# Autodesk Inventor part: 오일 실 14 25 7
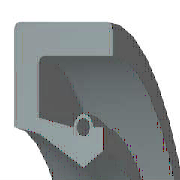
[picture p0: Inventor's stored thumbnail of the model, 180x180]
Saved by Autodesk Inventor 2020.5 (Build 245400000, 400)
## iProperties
Created: 2012-02
Part Number: 오일 실 14 25 7
Material: 고무
Description: 오일 실 - 스프링 장착, 금속 케이스 SM
Document SubType Name: Modeling
Standard: JIS B 2402
Designer: mdu-01
Standards Organization: JIS
Language: ko-KR
Size Designation: 14 25 7 A
Categories: <MemberInstance><Categories><Category DisplayName="샤프트 부품" InternalName="7f7aeb1f-a693-4053-b835-cee3144e0d98" Mnemonic="SHFT"><Category DisplayName="실링" Intern
Density: 0.93 g/cm^3
Appearance: Rubber-Black
IsCustomPart: 1
Author: mdu-01
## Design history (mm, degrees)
body "Solid1"
revolve "회전1" stored, may be unused: angle "d33" = 360 deg
fillet "모깎기1" dims "d34" = 0.35 (= 0.05 x b)
chamfer "모따기1" distance "d35" = 0.7 (= 0.1 x b); stored, may be unused: second distance "d36" = 0.35 (= 0.05 x b), angle "d41" = 45 deg
sketch "스케치2"
  geometry: L1 (8.336, -5.158)-(8.853, -7); L2 (7.786, -4.55)-(8.336, -5.158); L3 (7, -1.75)-(7.786, -4.55); L4 (7.733, -0.875)-(7, -1.75); L5 (8.963, -0.875)-(7.733, -0.875); L6 (8.963, -1.575)-(8.963, -0.875); L7 (8.963, -5.25)-(8.963, -2.975); L8 (10.3, -5.25)-(8.963, -5.25); L9 (11.4, -1.75)-(10.3, -5.25); L10 (11.4, 0)-(11.4, -1.75); L11 (12.5, 0)-(11.4, 0); L12 (12.5, -7)-(12.5, 0); L13 (8.853, -7)-(12.5, -7); L14 (0, -9.6)-(0, 1.6) reference; L15 (28, 0)-(14, 0) reference; A1 r 0.7 centre (8.963, -2.275) between (8.963, -2.975) and (8.963, -1.575)
  constraints: 26 end point, 4 horizontal, 4 vertical, 2 point on circle, 1 centre point, 1 collinear, 1 parallel
  dimensions: "d2" = 7 distance of L12.start L11.start (= b); "d4" = 0.875 vertical distance of L10.start L5.start (= 0.125 x b); "d6" = 1.1 distance of L11.start L10.start (= 0.1 x dd - 0.1 x Diam); "d8" = 1.75 distance of L10.start L9.start (= 0.25 x b); "d10" = 1.75 vertical distance of L8.start L1.end (= 0.25 x b); "d12" = 1.1 horizontal distance of L9.start L8.start (= 0.1 x dd - 0.1 x Diam); "d14" = 0.7 radius of A1 (= 0.1 x b); "d16" = 0 horizontal distance of A1.centre L7.end; "d18" = 0.7 distance of L6.start L5.start (= 0.1 x b); "d20" = 0.73333 horizontal distance of L4.start L3.start (= 0.0666667 x dd - 0.0666667 x Diam); "d22" = 0.11 horizontal distance of L7.start L1.end (= 0.01 x dd - 0.01 x Diam); "d24" = 0.875 vertical distance of L4.start L3.start (= 0.125 x b); "d26" = 2.8 vertical distance of L3.start L2.start (= 0.4 x b); "d28" = 0.78571 horizontal distance of L3.start L2.start (= 0.0714286 x dd - 0.0714286 x Diam); "d30" = 1.84211 vertical distance of L1.start L1.end (= 0.263158 x b); "d32" = 0.55 horizontal distance of L2.start L1.start (= 0.05 x dd - 0.05 x Diam); "d37" = 0 distance between parallel lines of L15 L11; "d38" = 12.5 distance between parallel lines of L14 L12 (= 0.5 x dd); "d39" = 7 distance from line of L14 L3.start (= 0.5 x Diam)
other parameters: "dd" = 25 [user parameter; used in 7 equation terms], "Diam" = 14 [user parameter; used in 7 equation terms], "b" = 7 [user parameter; used in 12 equation terms], "d1" = 8 (derived), "d3" = 1 (derived), "d5" = 2 (derived), "d7" = 2 (derived), "d9" = 2 (derived), "d11" = 2 (derived), "d13" = 0.8 (derived), "d15" = 0 (derived), "d17" = 0.8 (derived), "d19" = 1.33333 (derived), "d21" = 0.2 (derived), "d23" = 1 (derived), "d25" = 3.2 (derived), "d27" = 1.42857 (derived), "d29" = 2.10526 (derived), "d31" = 1 (derived), "d40" = 0
